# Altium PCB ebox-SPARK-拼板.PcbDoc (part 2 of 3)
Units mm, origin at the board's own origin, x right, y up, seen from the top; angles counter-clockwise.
Board outline 102 x 90 mm, 2 copper layers (Top Layer, Bottom Layer); 141 components, 68 nets, 621 pads, 146 vias.
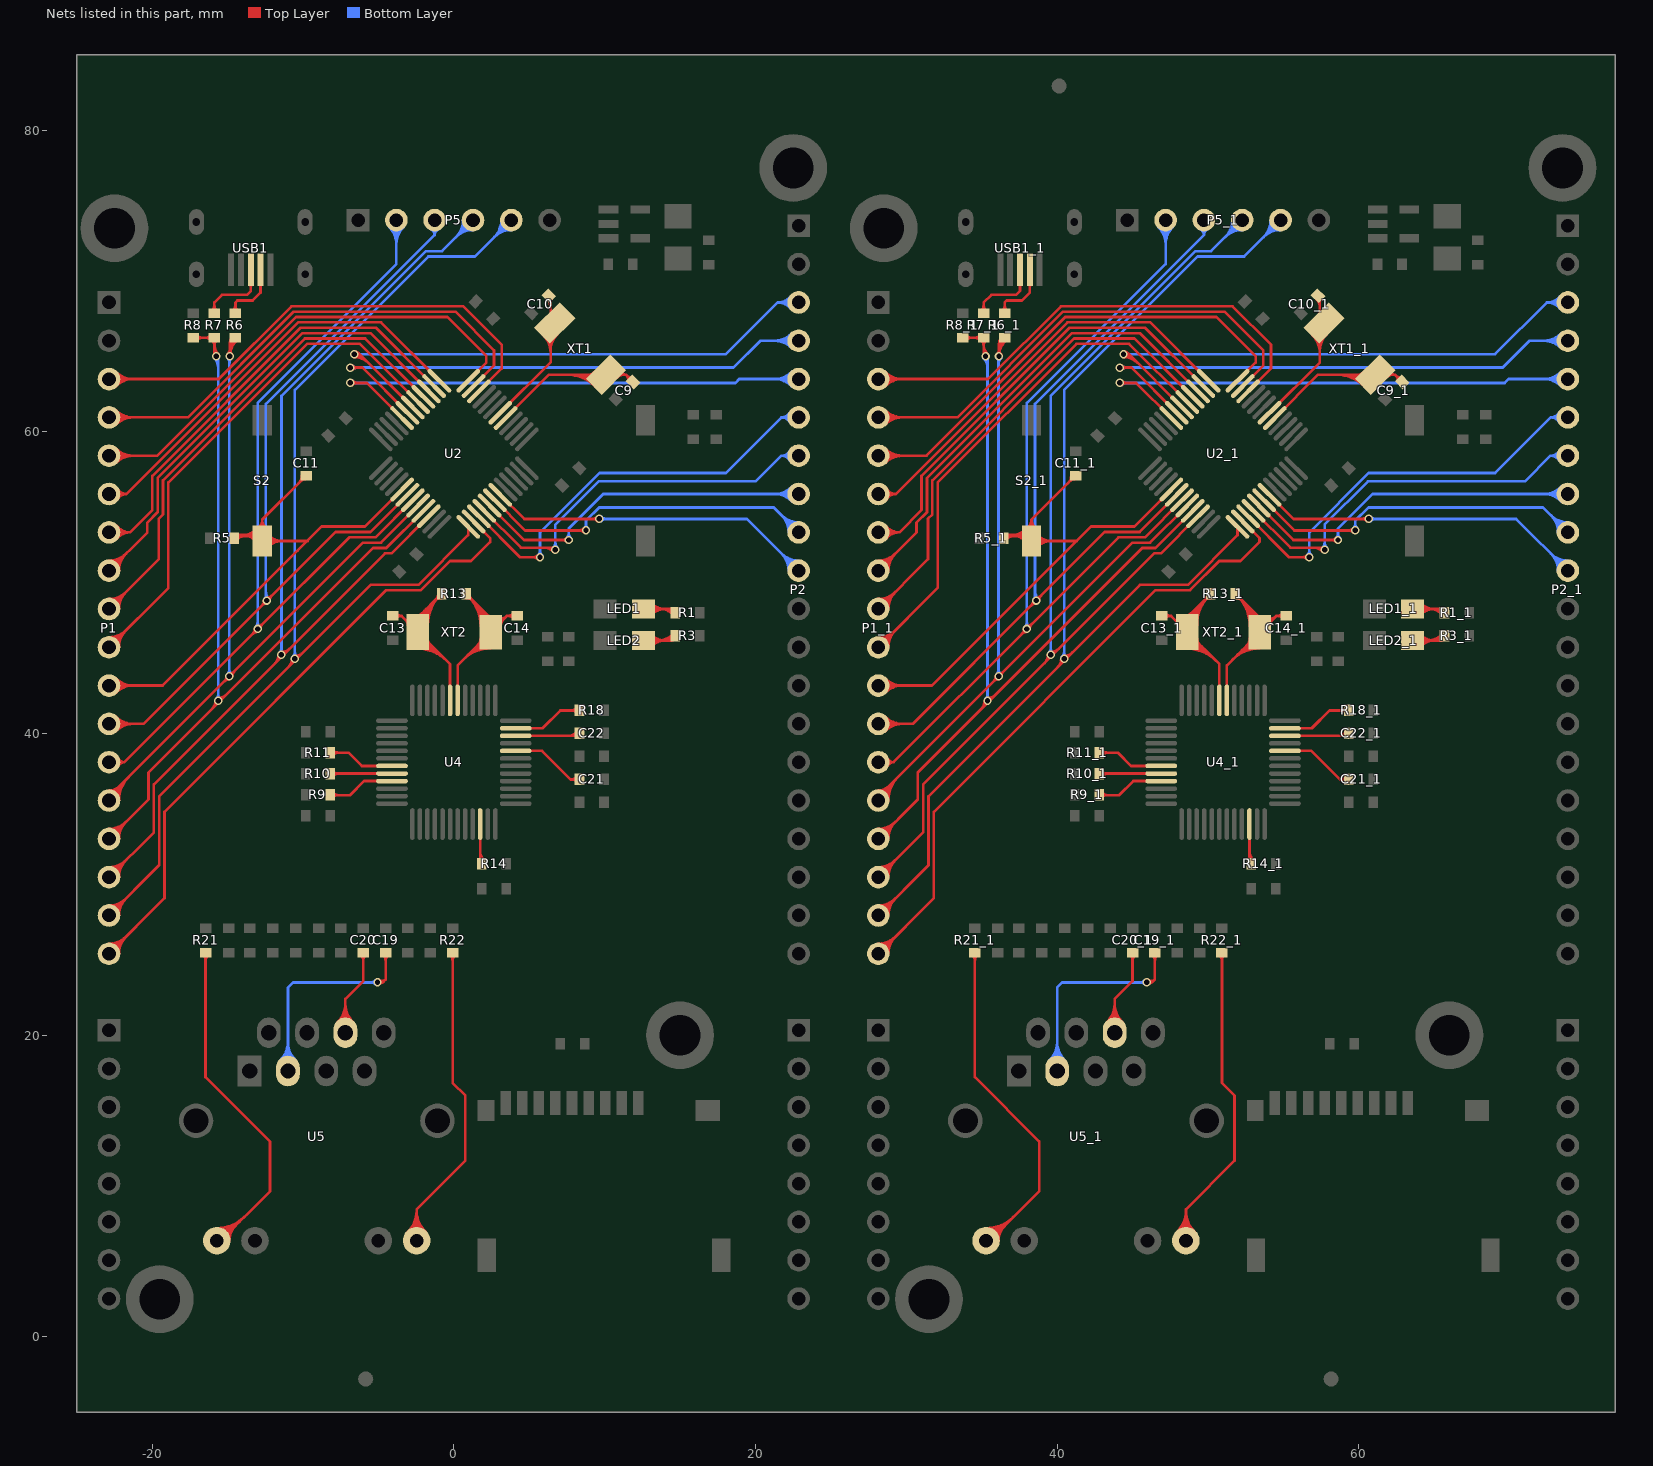
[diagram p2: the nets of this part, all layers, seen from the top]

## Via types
v1: diameter 0.559, hole 0.356, Top Layer to Bottom Layer, tented both sides, 140 vias
v2: diameter 1, hole 1, Top Layer to Bottom Layer, tented both sides, 4 vias
v3: diameter 1.27, hole 0.711, Top Layer to Bottom Layer, tented both sides, 2 vias

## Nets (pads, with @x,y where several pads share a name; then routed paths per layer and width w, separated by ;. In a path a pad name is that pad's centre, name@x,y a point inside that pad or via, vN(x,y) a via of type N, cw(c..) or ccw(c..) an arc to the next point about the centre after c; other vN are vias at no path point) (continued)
NetC9_1: C9.1 C9_1.1 U2.5 U2_1.5 XT1.1 XT1_1.1 | length 37.6
  Top Layer w0.178: U2.5@3.429,60.916 6.303,63.79 XT1.1@10.088,63.79 11.401,63.79 ; 7.527,63.79 cw(c7.527,61.228) XT1.1@9.338,63.04 ; 7.956,63.79 cw(c7.956,61.657) XT1.1@9.464,63.165 ; 8.385,63.79 cw(c8.385,62.087) XT1.1@9.589,63.291 ; 8.814,63.79 cw(c8.814,62.516) XT1.1@9.715,63.417 ; 8.892,63.79 ccw(c8.892,64.42) XT1.1@9.338,63.974 ; XT1.1@10.839,63.605 cw(c11.284,63.159) 11.284,63.79 ; XT1.1@10.853,64.115 ccw(c11.207,64.145) 11.207,63.79 ; XT1.1@11.03,64.13 ccw(c11.401,64.162) 11.401,63.79 ; C9.1@11.604,63.358 ccw(c11.052,63.358) 11.443,63.748 ccw(c11.833,64.138) C9.1@11.833,63.586 ; C9.1@11.878,63.313 11.401,63.79 ; U2_1.5@54.429,60.916 57.303,63.79 XT1_1.1@61.088,63.79 62.401,63.79 ; 58.527,63.79 cw(c58.527,61.228) XT1_1.1@60.338,63.04 ; 58.956,63.79 cw(c58.956,61.657) XT1_1.1@60.464,63.165 ; 59.385,63.79 cw(c59.385,62.087) XT1_1.1@60.589,63.291 ; 59.814,63.79 cw(c59.814,62.516) XT1_1.1@60.715,63.417 ; 59.892,63.79 ccw(c59.892,64.42) XT1_1.1@60.338,63.974 ; XT1_1.1@61.839,63.605 cw(c62.284,63.159) 62.284,63.79 ; XT1_1.1@61.853,64.115 ccw(c62.207,64.145) 62.207,63.79 ; XT1_1.1@62.03,64.13 ccw(c62.401,64.162) 62.401,63.79 ; C9_1.1@62.604,63.358 ccw(c62.052,63.358) 62.443,63.748 ccw(c62.833,64.138) C9_1.1@62.833,63.586 ; C9_1.1@62.878,63.313 62.401,63.79
NetC10_1: C10.1 C10_1.1 U2.6 U2_1.6 XT1.2 XT1_1.2 | length 30.8
  Top Layer w0.178: U2.6@3.076,61.269 6.417,64.61 6.417,68.647 6.417,68.901 C10.1@6.29,69.028 ; XT1.2@5.908,66.435 cw(c4.68,65.207) 6.417,65.207 ; XT1.2@6.034,66.56 cw(c5.109,65.636) 6.417,65.636 ; XT1.2@6.159,66.686 cw(c5.538,66.065) XT1.2@6.417,66.065 ; C10.1@6.173,68.821 cw(c5.585,68.233) 6.417,68.233 ; C10.1@6.299,68.947 cw(c6.014,68.662) C10.1@6.417,68.662 ; 6.417,65.406 cw(c7.872,65.406) XT1.2@6.843,66.435 ; 6.417,65.835 cw(c7.443,65.835) XT1.2@6.717,66.56 ; C10.1@6.417,68.629 cw(c6.688,68.629) C10.1@6.496,68.821 ; U2_1.6@54.076,61.269 57.417,64.61 57.417,68.647 57.417,68.901 C10_1.1@57.29,69.028 ; XT1_1.2@56.908,66.435 cw(c55.68,65.207) 57.417,65.207 ; XT1_1.2@57.034,66.56 cw(c56.109,65.636) 57.417,65.636 ; XT1_1.2@57.159,66.686 cw(c56.538,66.065) XT1_1.2@57.417,66.065 ; C10_1.1@57.173,68.821 cw(c56.585,68.233) 57.417,68.233 ; C10_1.1@57.299,68.947 cw(c57.014,68.662) C10_1.1@57.417,68.662 ; 57.417,65.406 cw(c58.872,65.406) XT1_1.2@57.843,66.435 ; 57.417,65.835 cw(c58.443,65.835) XT1_1.2@57.717,66.56 ; C10_1.1@57.417,68.629 cw(c57.688,68.629) C10_1.1@57.496,68.821
NetC13_2: C13.2 C13_1.2 R13.2 R13_1.2 U4.31 U4_1.31 XT2.2 XT2_1.2 | length 55.4
  Top Layer w0.178: C13.2@-4.064,47.803 -3.454,47.803 ; C13.2@-3.838,47.642 cw(c-3.454,47.265) -3.454,47.803 ; C13.2@-3.838,47.963 ccw(c-3.454,48.341) -3.454,47.803 ; -3.198,47.546 cw(c-3.558,47.186) XT2.2@-3.049,47.186 ; XT2.2@-2.438,47.186 cw(c-1.315,47.186) -2.109,47.98 ; XT2.2@-2.388,45.625 cw(c-2.388,42.942) -0.491,44.839 ; XT2.2@-2.388,45.803 cw(c-2.388,43.55) -0.794,45.143 ; XT2.2@-2.388,45.98 cw(c-2.388,44.157) -1.098,45.446 ; XT2.2@-2.388,46.158 cw(c-2.388,44.764) -1.401,45.75 ; XT2.2@-2.388,47.847 ccw(c-2.388,48.199) -2.139,47.95 ; XT2.2@-2.26,47.186 cw(c-0.708,47.186) -1.805,48.283 ; XT2.2@-2.082,47.186 cw(c-0.101,47.186) -1.502,48.587 ; XT2.2@-1.904,47.186 cw(c0.506,47.186) -1.198,48.891 ; XT2.2@-1.727,46.286 ccw(c-1.217,46.286) -1.577,45.926 ; XT2.2@-1.727,47.186 cw(c1.113,47.186) R13.2@-0.895,49.194 ; -1.311,48.777 cw(c-0.813,48.279) R13.2@-0.813,48.984 ; -1.158,48.931 ccw(c-1.44,49.212) R13.2@-1.041,49.212 ; R13.2@-0.813,49.276 -2.388,47.701 XT2.2@-2.388,46.736 ; U4.31@-0.25,42.2 -0.25,44.598 XT2.2@-2.388,46.736 ; C13_1.2@46.936,47.803 47.546,47.803 XT2_1.2@48.612,46.736 ; C13_1.2@47.162,47.642 cw(c47.546,47.265) 47.546,47.803 cw(c47.546,48.341) C13_1.2@47.162,47.963 ; 47.802,47.546 cw(c47.442,47.186) XT2_1.2@47.951,47.186 ; XT2_1.2@48.562,47.186 cw(c49.685,47.186) 48.891,47.98 ; XT2_1.2@48.612,45.625 cw(c48.612,42.942) 50.509,44.839 ; XT2_1.2@48.612,45.803 cw(c48.612,43.55) 50.206,45.143 ; XT2_1.2@48.612,45.98 cw(c48.612,44.157) 49.902,45.446 ; XT2_1.2@48.612,46.158 cw(c48.612,44.764) 49.599,45.75 ; XT2_1.2@48.612,47.847 ccw(c48.612,48.199) 48.861,47.95 ; XT2_1.2@48.74,47.186 cw(c50.292,47.186) 49.195,48.283 ; XT2_1.2@48.918,47.186 cw(c50.899,47.186) 49.498,48.587 ; XT2_1.2@49.096,47.186 cw(c51.506,47.186) 49.802,48.891 ; XT2_1.2@49.273,46.286 ccw(c49.783,46.286) 49.423,45.926 ; XT2_1.2@49.273,47.186 cw(c52.113,47.186) R13_1.2@50.105,49.194 ; 49.689,48.777 cw(c50.187,48.279) R13_1.2@50.187,48.984 ; 49.842,48.931 ccw(c49.56,49.212) R13_1.2@49.959,49.212 ; R13_1.2@50.187,49.276 48.612,47.701 XT2_1.2@48.612,46.736 ; U4_1.31@50.75,42.2 50.75,44.598 XT2_1.2@48.612,46.736 ; -3.454,47.803 XT2.2@-2.388,46.736
NetC14_1: C14.1 C14_1.1 R13.1 R13_1.1 U4.30 U4_1.30 XT2.1 XT2_1.1 | length 60.2
  Top Layer w0.178: U4.30@0.25,42.2 0.25,44.522 XT2.1@2.438,46.711 ; 0.627,44.899 cw(c2.438,43.088) XT2.1@2.438,45.649 ; R13.1@0.813,48.984 cw(c0.813,48.279) 1.311,48.777 ; R13.1@0.813,49.276 2.438,47.65 XT2.1@2.438,46.711 ; R13.1@0.928,49.161 cw(c-1.122,47.111) XT2.1@1.777,47.111 ; 0.931,45.203 cw(c2.438,43.695) XT2.1@2.438,45.827 ; R13.1@1.041,49.212 ccw(c1.44,49.212) 1.158,48.931 ; 1.232,48.857 cw(c-0.515,47.111) XT2.1@1.955,47.111 ; 1.234,45.506 cw(c2.438,44.302) XT2.1@2.438,46.005 ; 1.535,48.554 cw(c0.092,47.111) XT2.1@2.133,47.111 ; 1.538,45.81 cw(c2.438,44.909) XT2.1@2.438,46.183 ; 1.593,45.865 ccw(c1.147,46.311) XT2.1@1.777,46.311 ; 1.839,48.25 cw(c0.699,47.111) XT2.1@2.311,47.111 ; 2.142,47.947 cw(c1.306,47.111) XT2.1@2.489,47.111 ; XT2.1@2.231,47.857 ccw(c2.438,48.065) XT2.1@2.438,47.772 ; XT2.1@2.585,47.379 ccw(c2.831,47.83) 3.194,47.467 ; XT2.1@2.67,47.535 ccw(c2.949,48.048) 3.363,47.635 ; XT2.1@2.755,47.691 ccw(c3.068,48.265) 3.531,47.803 ; XT2.1@3.099,47.111 cw(c3.73,47.111) 3.284,47.556 ; C14.1@3.966,47.641 ccw(c3.576,47.251) 3.576,47.803 ccw(c3.576,48.355) C14.1@3.966,47.964 ; C14.1@4.191,47.803 3.531,47.803 ; U4_1.30@51.25,42.2 51.25,44.522 XT2_1.1@53.438,46.711 ; 51.627,44.899 cw(c53.438,43.088) XT2_1.1@53.438,45.649 ; R13_1.1@51.813,48.984 cw(c51.813,48.279) 52.311,48.777 ; R13_1.1@51.813,49.276 53.438,47.65 XT2_1.1@53.438,46.711 ; R13_1.1@51.928,49.161 cw(c49.878,47.111) XT2_1.1@52.777,47.111 ; 51.931,45.203 cw(c53.438,43.695) XT2_1.1@53.438,45.827 ; R13_1.1@52.041,49.212 ccw(c52.44,49.212) 52.158,48.931 ; 52.232,48.857 cw(c50.485,47.111) XT2_1.1@52.955,47.111 ; 52.234,45.506 cw(c53.438,44.302) XT2_1.1@53.438,46.005 ; 52.535,48.554 cw(c51.092,47.111) XT2_1.1@53.133,47.111 ; 52.538,45.81 cw(c53.438,44.909) XT2_1.1@53.438,46.183 ; 52.593,45.865 ccw(c52.147,46.311) XT2_1.1@52.777,46.311 ; 52.839,48.25 cw(c51.699,47.111) XT2_1.1@53.311,47.111 ; 53.142,47.947 cw(c52.306,47.111) XT2_1.1@53.489,47.111 ; XT2_1.1@53.231,47.857 ccw(c53.438,48.065) XT2_1.1@53.438,47.772 ; XT2_1.1@53.585,47.379 ccw(c53.831,47.83) 54.194,47.467 ; XT2_1.1@53.67,47.535 ccw(c53.949,48.048) 54.363,47.635 ; XT2_1.1@53.755,47.691 ccw(c54.068,48.265) 54.531,47.803 ; XT2_1.1@54.099,47.111 cw(c54.73,47.111) 54.284,47.556 ; C14_1.1@54.966,47.641 ccw(c54.576,47.251) 54.576,47.803 ccw(c54.576,48.355) C14_1.1@54.966,47.964 ; C14_1.1@55.191,47.803 54.531,47.803 ; XT2.1@2.438,46.711 3.531,47.803 ; XT2_1.1@53.438,46.711 54.531,47.803
NetC19_1: C19.1 C19_1.1 U5.3 U5_1.3 | length 44.8
  Top Layer w0.178: v1(-5.061,23.509) -4.711,23.509 -4.521,23.698 ; v1@-5.054,23.519 ccw(c-4.88,23.761) -4.669,23.55 ; v1@-4.95,23.663 ccw(c-4.756,23.933) -4.521,23.698 ; C19.1@-4.683,25.315 cw(c-5.073,24.924) -4.521,24.924 cw(c-3.969,24.924) C19.1@-4.36,25.315 ; C19.1@-4.521,25.476 -4.521,23.698 ; v1(45.939,23.509) 46.289,23.509 46.479,23.698 ; v1@45.946,23.519 ccw(c46.12,23.761) 46.331,23.55 ; v1@46.05,23.663 ccw(c46.244,23.933) 46.479,23.698 ; C19_1.1@46.317,25.315 cw(c45.927,24.924) 46.479,24.924 cw(c47.031,24.924) C19_1.1@46.64,25.315 ; C19_1.1@46.479,25.476 46.479,23.698
  Bottom Layer w0.178: U5.3@-11.493,18.35 ccw(c-12.685,19.543) -10.999,19.543 ccw(c-9.312,19.543) U5.3@-10.505,18.35 ; U5.3@-11.367,18.224 ccw(c-12.256,19.113) -10.999,19.113 ccw(c-9.742,19.113) U5.3@-10.63,18.224 ; U5.3@-11.241,18.099 ccw(c-11.826,18.684) -10.999,18.684 ccw(c-10.171,18.684) U5.3@-10.756,18.099 ; U5.3@-10.999,17.628 -10.999,23.164 -10.668,23.495 -5.064,23.495 -5.061,23.498 v1(-5.061,23.509) ; -5.554,23.495 ccw(c-5.554,24.001) v1@-5.196,23.643 ; -5.488,23.495 cw(c-5.488,23.081) v1@-5.196,23.374 ; U5_1.3@39.507,18.35 ccw(c38.315,19.543) 40.001,19.543 ccw(c41.688,19.543) U5_1.3@40.495,18.35 ; U5_1.3@39.633,18.224 ccw(c38.744,19.113) 40.001,19.113 ccw(c41.258,19.113) U5_1.3@40.37,18.224 ; U5_1.3@39.759,18.099 ccw(c39.174,18.684) 40.001,18.684 ccw(c40.829,18.684) U5_1.3@40.244,18.099 ; U5_1.3@40.001,17.628 40.001,23.164 40.332,23.495 45.936,23.495 45.939,23.498 v1(45.939,23.509) ; 45.446,23.495 ccw(c45.446,24.001) v1@45.804,23.643 ; 45.512,23.495 cw(c45.512,23.081) v1@45.804,23.374
NetC20_1: C20.1 C20_1.1 U5.6 U5_1.6 | length 29.6
  Top Layer w0.178: U5.6@-7.683,20.89 ccw(c-8.875,22.083) -7.189,22.083 ccw(c-5.502,22.083) U5.6@-6.695,20.89 ; U5.6@-7.557,20.764 ccw(c-8.446,21.653) -7.189,21.653 ccw(c-5.932,21.653) U5.6@-6.82,20.764 ; U5.6@-7.431,20.639 ccw(c-8.016,21.224) -7.189,21.224 ccw(c-6.361,21.224) U5.6@-6.946,20.639 ; U5.6@-7.189,20.168 -7.189,22.402 -6.003,23.588 C20.1@-6.003,25.476 -6.003,24.13 ; U5_1.6@43.317,20.89 ccw(c42.125,22.083) 43.811,22.083 ccw(c45.498,22.083) U5_1.6@44.305,20.89 ; U5_1.6@43.443,20.764 ccw(c42.554,21.653) 43.811,21.653 ccw(c45.068,21.653) U5_1.6@44.18,20.764 ; U5_1.6@43.569,20.639 ccw(c42.984,21.224) 43.811,21.224 ccw(c44.639,21.224) U5_1.6@44.054,20.639 ; U5_1.6@43.811,20.168 43.811,22.402 44.997,23.588 C20_1.1@44.997,25.476 44.997,24.13 ; -6.003,24.924 cw(c-5.451,24.924) -5.841,25.315 ccw(c-5.451,24.924) -6.003,24.924 ; -6.003,24.924 ccw(c-6.555,24.924) -6.165,25.315 cw(c-6.555,24.924) -6.003,24.924 ; 44.997,24.924 cw(c45.549,24.924) 45.159,25.315 ccw(c45.549,24.924) 44.997,24.924 ; 44.997,24.924 ccw(c44.445,24.924) 44.835,25.315 cw(c44.445,24.924) 44.997,24.924
NetC21_2: C21.2 C21_1.2 U4.20 U4_1.20 | length 11.8
  Top Layer w0.178: U4.20@4.1,38.85 5.854,38.85 7.747,36.957 C21.2@8.331,36.957 ; C21.2@8.17,36.795 ccw(c7.779,36.405) 7.779,36.957 ccw(c7.779,37.509) C21.2@8.17,37.119 ; U4_1.20@55.1,38.85 56.854,38.85 58.747,36.957 C21_1.2@59.331,36.957 ; C21_1.2@59.17,36.795 ccw(c58.779,36.405) 58.779,36.957 ccw(c58.779,37.509) C21_1.2@59.17,37.119
NetC22_2: C22.2 C22_1.2 U4.22 U4_1.22 | length 11
  Top Layer w0.178: U4.22@4.1,39.85 8.176,39.85 C22.2@8.331,40.005 ; 7.558,39.85 ccw(c7.558,40.714) C22.2@8.17,40.103 ; 7.988,39.85 ccw(c7.988,40.285) C22.2@8.295,39.977 ; 8,39.85 cw(c8,39.611) C22.2@8.17,39.78 ; U4_1.22@55.1,39.85 59.176,39.85 C22_1.2@59.331,40.005 ; 58.558,39.85 ccw(c58.558,40.714) C22_1.2@59.17,40.103 ; 58.988,39.85 ccw(c58.988,40.285) C22_1.2@59.295,39.977 ; 59,39.85 cw(c59,39.611) C22_1.2@59.17,39.78
NetLED1_A: LED1.A LED1_1.A R1.2 R1_1.2 | length 13.6
  Top Layer w0.178: LED1.A@12.573,48.26 R1.2@14.427,48.26 ; LED1.A@12.963,48.007 cw(c13.575,47.395) 13.575,48.26 cw(c13.575,49.125) LED1.A@12.963,48.513 ; LED1.A@13.089,47.881 cw(c14.004,46.966) 14.004,48.26 cw(c14.004,49.554) LED1.A@13.089,48.639 ; 13.669,48.26 cw(c13.669,47.058) R1.2@14.52,47.908 ; 14.099,48.26 cw(c14.099,47.487) R1.2@14.645,48.034 ; LED1_1.A@63.573,48.26 R1_1.2@65.427,48.26 ; LED1_1.A@63.963,48.007 cw(c64.575,47.395) 64.575,48.26 cw(c64.575,49.125) LED1_1.A@63.963,48.513 ; LED1_1.A@64.089,47.881 cw(c65.004,46.966) 65.004,48.26 cw(c65.004,49.554) LED1_1.A@64.089,48.639 ; 64.669,48.26 cw(c64.669,47.058) R1_1.2@65.52,47.908 ; 65.099,48.26 cw(c65.099,47.487) R1_1.2@65.645,48.034
NetLED2_A: LED2.A LED2_1.A R3.2 R3_1.2 | length 15.9
  Top Layer w0.178: LED2.A@12.573,46.164 14.364,46.164 R3.2@14.681,46.482 ; LED2.A@12.963,45.911 cw(c13.575,45.299) 13.575,46.164 cw(c13.575,47.03) LED2.A@12.963,46.418 ; LED2.A@13.089,45.785 cw(c14.004,44.87) 14.004,46.164 cw(c14.004,47.459) LED2.A@13.089,46.544 ; 13.516,46.164 ccw(c13.516,47.584) R3.2@14.52,46.58 ; 13.945,46.164 ccw(c13.945,47.154) R3.2@14.645,46.454 ; R3.2@14.375,46.164 ccw(c14.375,46.725) R3.2@14.771,46.329 ; LED2_1.A@63.573,46.164 65.364,46.164 R3_1.2@65.681,46.482 ; LED2_1.A@63.963,45.911 cw(c64.575,45.299) 64.575,46.164 cw(c64.575,47.03) LED2_1.A@63.963,46.418 ; LED2_1.A@64.089,45.785 cw(c65.004,44.87) 65.004,46.164 cw(c65.004,47.459) LED2_1.A@64.089,46.544 ; 64.516,46.164 ccw(c64.516,47.584) R3_1.2@65.52,46.58 ; 64.945,46.164 ccw(c64.945,47.154) R3_1.2@65.645,46.454 ; R3_1.2@65.375,46.164 ccw(c65.375,46.725) R3_1.2@65.771,46.329
NetR6_2: R6.2 R6_1.2 USB1.2 USB1_1.2 | length 11.2
  Top Layer w0.178: R6.2@-14.64,68.03 ccw(c-15.03,68.421) -14.478,68.421 ccw(c-13.926,68.421) R6.2@-14.316,68.03 ; R6.2@-14.478,67.869 -14.478,68.58 -14.351,68.707 -13.335,68.707 -12.812,69.23 USB1.2@-12.812,70.881 ; USB1.2@-12.891,69.8 cw(c-13.08,69.611) -12.812,69.611 cw(c-12.544,69.611) USB1.2@-12.733,69.8 ; R6_1.2@36.36,68.03 ccw(c35.97,68.421) 36.522,68.421 ccw(c37.074,68.421) R6_1.2@36.684,68.03 ; R6_1.2@36.522,67.869 36.522,68.58 36.649,68.707 37.665,68.707 38.188,69.23 USB1_1.2@38.188,70.881 ; USB1_1.2@38.109,69.8 cw(c37.92,69.611) 38.188,69.611 cw(c38.456,69.611) USB1_1.2@38.267,69.8
NetR7_2: R7.2 R7_1.2 USB1.3 USB1_1.3 | length 12.5
  Top Layer w0.178: R7.2@-16.037,68.03 ccw(c-16.427,68.421) -15.875,68.421 ccw(c-15.323,68.421) R7.2@-15.713,68.03 ; R7.2@-15.875,67.869 -15.875,68.58 -15.367,69.088 -13.716,69.088 -13.462,69.342 USB1.3@-13.462,70.881 ; USB1.3@-13.541,69.8 cw(c-13.73,69.611) -13.462,69.611 cw(c-13.194,69.611) USB1.3@-13.383,69.8 ; R7_1.2@34.963,68.03 ccw(c34.573,68.421) 35.125,68.421 ccw(c35.677,68.421) R7_1.2@35.287,68.03 ; R7_1.2@35.125,67.869 35.125,68.58 35.633,69.088 37.284,69.088 37.538,69.342 USB1_1.3@37.538,70.881 ; USB1_1.3@37.459,69.8 cw(c37.27,69.611) 37.538,69.611 cw(c37.806,69.611) USB1_1.3@37.617,69.8
NetR9_1: R9.1 R9_1.1 U4.45 U4_1.45 | length 10.7
  Top Layer w0.178: R9.1@-8.204,35.909 -6.89,35.909 -5.949,36.85 U4.45@-4.1,36.85 ; R9.1@-8.043,35.779 cw(c-7.729,35.466) -7.729,35.909 ; R9.1@-8.043,36.103 ccw(c-7.576,36.57) -7.576,35.909 ; R9_1.1@42.796,35.909 44.11,35.909 45.051,36.85 U4_1.45@46.9,36.85 ; R9_1.1@42.957,35.779 cw(c43.271,35.466) 43.271,35.909 ; R9_1.1@42.957,36.103 ccw(c43.424,36.57) 43.424,35.909
NetR10_1: R10.1 R10_1.1 U4.44 U4_1.44 | length 10
  Top Layer w0.178: R10.1@-8.204,37.338 -8.192,37.35 U4.44@-4.1,37.35 ; R10.1@-8.043,37.176 cw(c-7.623,36.757) -7.623,37.35 ; R10.1@-8.043,37.5 ccw(c-7.681,37.861) -7.681,37.35 ; R10_1.1@42.796,37.338 42.808,37.35 U4_1.44@46.9,37.35 ; R10_1.1@42.957,37.176 cw(c43.377,36.757) 43.377,37.35 ; R10_1.1@42.957,37.5 ccw(c43.319,37.861) 43.319,37.35
NetR11_1: R11.1 R11_1.1 U4.43 U4_1.43 | length 10.7
  Top Layer w0.178: R11.1@-8.204,38.735 -6.985,38.735 -6.1,37.85 U4.43@-4.1,37.85 ; R11.1@-8.043,38.573 cw(c-7.652,38.183) -7.652,38.735 cw(c-7.652,39.287) R11.1@-8.043,38.897 ; R11_1.1@42.796,38.735 44.015,38.735 44.9,37.85 U4_1.43@46.9,37.85 ; R11_1.1@42.957,38.573 cw(c43.348,38.183) 43.348,38.735 cw(c43.348,39.287) R11_1.1@42.957,38.897
NetR14_1: R14.1 R14_1.1 U4.10 U4_1.10 | length 7.3
  Top Layer w0.178: R14.1@1.693,31.594 ccw(c1.554,31.733) R14.1@1.75,31.733 ; R14.1@1.75,31.6 U4.10@1.75,34 ; 1.75,31.807 ccw(c2.228,31.807) R14.1@1.89,31.468 ; 1.75,32.236 ccw(c2.658,32.236) R14.1@2.016,31.594 ; R14_1.1@52.693,31.594 ccw(c52.554,31.733) R14_1.1@52.75,31.733 ; R14_1.1@52.75,31.6 U4_1.10@52.75,34 ; 52.75,31.807 ccw(c53.228,31.807) R14_1.1@52.89,31.468 ; 52.75,32.236 ccw(c53.658,32.236) R14_1.1@53.016,31.594
NetR18_2: R18.2 R18_1.2 U4.23 U4_1.23 | length 11.2
  Top Layer w0.178: U4.23@4.1,40.35 5.878,40.35 7.057,41.529 R18.2@8.331,41.529 ; R18.2@8.17,41.367 ccw(c7.779,40.977) 7.779,41.529 ccw(c7.779,42.081) R18.2@8.17,41.691 ; U4_1.23@55.1,40.35 56.878,40.35 58.057,41.529 R18_1.2@59.331,41.529 ; R18_1.2@59.17,41.367 ccw(c58.779,40.977) 58.779,41.529 ccw(c58.779,42.081) R18_1.2@59.17,41.691
NetR21_2: R21.2 R21_1.2 U5.9 U5_1.9 | length 62.6
  Top Layer w0.178: R21.2@-16.621,25.315 cw(c-17.011,24.924) -16.459,24.924 cw(c-15.907,24.924) R21.2@-16.298,25.315 ; R21.2@-16.459,25.476 -16.459,17.221 -12.192,12.954 -12.192,9.652 -15.466,6.378 U5.9@-15.714,6.378 ; U5.9@-15.714,6.67 ccw(c-15.714,7.972) -14.793,7.051 ; U5.9@-15.714,6.848 ccw(c-15.714,8.579) -14.489,7.355 ; U5.9@-15.714,7.025 ccw(c-15.714,9.186) -14.186,7.658 ; U5.9@-15.714,7.203 ccw(c-15.714,9.793) -13.882,7.962 ; U5.9@-15.066,6.378 cw(c-14.099,6.378) -14.783,7.061 ; U5.9@-14.888,6.378 cw(c-13.492,6.378) -14.479,7.365 ; R21_1.2@34.379,25.315 cw(c33.989,24.924) 34.541,24.924 cw(c35.093,24.924) R21_1.2@34.702,25.315 ; R21_1.2@34.541,25.476 34.541,17.221 38.808,12.954 38.808,9.652 35.534,6.378 U5_1.9@35.286,6.378 ; U5_1.9@35.286,6.67 ccw(c35.286,7.972) 36.207,7.051 ; U5_1.9@35.286,6.848 ccw(c35.286,8.579) 36.511,7.355 ; U5_1.9@35.286,7.025 ccw(c35.286,9.186) 36.814,7.658 ; U5_1.9@35.286,7.203 ccw(c35.286,9.793) 37.118,7.962 ; U5_1.9@35.934,6.378 cw(c36.901,6.378) 36.217,7.061 ; U5_1.9@36.112,6.378 cw(c37.508,6.378) 36.521,7.365
NetR22_2: R22.2 R22_1.2 U5.12 U5_1.12 | length 58
  Top Layer w0.178: U5.12@-3.048,6.961 ccw(c-4.457,8.371) -2.464,8.371 ccw(c-0.471,8.371) U5.12@-1.88,6.961 ; U5.12@-2.922,6.836 ccw(c-4.028,7.941) -2.464,7.941 ccw(c-0.901,7.941) U5.12@-2.006,6.836 ; U5.12@-2.796,6.71 ccw(c-3.599,7.512) -2.464,7.512 ccw(c-1.33,7.512) U5.12@-2.132,6.71 ; U5.12@-2.464,6.378 -2.464,8.458 0.762,11.684 0.762,16.002 -0.076,16.84 -0.076,18.085 -0.076,18.161 R22.2@-0.076,25.476 ; R22.2@-0.238,25.315 cw(c-0.628,24.924) -0.076,24.924 cw(c0.476,24.924) R22.2@0.085,25.315 ; U5_1.12@47.952,6.961 ccw(c46.543,8.371) 48.536,8.371 ccw(c50.529,8.371) U5_1.12@49.12,6.961 ; U5_1.12@48.078,6.836 ccw(c46.972,7.941) 48.536,7.941 ccw(c50.099,7.941) U5_1.12@48.994,6.836 ; U5_1.12@48.204,6.71 ccw(c47.401,7.512) 48.536,7.512 ccw(c49.67,7.512) U5_1.12@48.868,6.71 ; U5_1.12@48.536,6.378 48.536,8.458 51.762,11.684 51.762,16.002 50.924,16.84 50.924,18.085 50.924,18.161 R22_1.2@50.924,25.476 ; R22_1.2@50.762,25.315 cw(c50.372,24.924) 50.924,24.924 cw(c51.476,24.924) R22_1.2@51.085,25.315
PA0: P1.3 P1_1.3 U2.10 U2_1.10 | length 74.3
  Top Layer w0.178: P1.3@-22.86,63.5 -15.585,63.5 -10.759,68.326 0.635,68.326 3.175,65.786 3.175,64.197 U2.10@1.662,62.684 ; P1.3@-22.518,63.158 cw(c-21.693,62.333) -21.693,63.5 cw(c-21.693,64.667) P1.3@-22.518,63.842 ; P1.3@-22.393,63.033 cw(c-21.264,61.904) -21.264,63.5 cw(c-21.264,65.096) P1.3@-22.393,63.967 ; P1_1.3@28.14,63.5 35.415,63.5 40.241,68.326 51.635,68.326 54.175,65.786 54.175,64.197 U2_1.10@52.662,62.684 ; P1_1.3@28.482,63.158 cw(c29.307,62.333) 29.307,63.5 cw(c29.307,64.667) P1_1.3@28.482,63.842 ; P1_1.3@28.607,63.033 cw(c29.736,61.904) 29.736,63.5 cw(c29.736,65.096) P1_1.3@28.607,63.967
PA1: P1.4 P1_1.4 U2.11 U2_1.11 | length 73.5
  Top Layer w0.178: P1.4@-22.86,60.96 -17.622,60.96 -10.612,67.97 0.102,67.97 2.667,65.405 2.667,64.396 U2.11@1.308,63.037 ; P1.4@-22.518,60.618 cw(c-21.693,59.793) -21.693,60.96 cw(c-21.693,62.127) P1.4@-22.518,61.302 ; P1.4@-22.393,60.493 cw(c-21.264,59.364) -21.264,60.96 cw(c-21.264,62.556) P1.4@-22.393,61.427 ; P1_1.4@28.14,60.96 33.378,60.96 40.388,67.97 51.102,67.97 53.667,65.405 53.667,64.396 U2_1.11@52.308,63.037 ; P1_1.4@28.482,60.618 cw(c29.307,59.793) 29.307,60.96 cw(c29.307,62.127) P1_1.4@28.482,61.302 ; P1_1.4@28.607,60.493 cw(c29.736,59.364) 29.736,60.96 cw(c29.736,62.556) P1_1.4@28.607,61.427
PA2: P1.5 P1_1.5 U2.12 U2_1.12 | length 72.7
  Top Layer w0.178: P1.5@-22.86,58.42 -19.659,58.42 -10.465,67.615 -0.432,67.615 2.159,65.024 2.159,64.595 U2.12@0.955,63.391 ; P1.5@-22.518,58.078 cw(c-21.693,57.253) -21.693,58.42 cw(c-21.693,59.587) P1.5@-22.518,58.762 ; P1.5@-22.393,57.953 cw(c-21.264,56.824) -21.264,58.42 cw(c-21.264,60.016) P1.5@-22.393,58.887 ; P1_1.5@28.14,58.42 31.341,58.42 40.535,67.615 50.568,67.615 53.159,65.024 53.159,64.595 U2_1.12@51.955,63.391 ; P1_1.5@28.482,58.078 cw(c29.307,57.253) 29.307,58.42 cw(c29.307,59.587) P1_1.5@28.482,58.762 ; P1_1.5@28.607,57.953 cw(c29.736,56.824) 29.736,58.42 cw(c29.736,60.016) P1_1.5@28.607,58.887
PA3: P1.6 P1_1.6 U2.13 U2_1.13 | length 61.4
  Top Layer w0.178: P1.6@-22.86,55.88 -21.697,55.88 ; P1.6@-22.445,55.633 cw(c-22.01,55.373) -22.01,55.88 cw(c-22.01,56.387) P1.6@-22.445,56.127 ; P1.6@-22.292,55.542 cw(c-21.697,55.187) -21.697,55.88 ; P1.6@-22.292,56.218 ccw(c-21.697,56.573) -21.697,55.88 ; U2.13@-0.955,63.391 -4.823,67.259 -10.317,67.259 -21.697,55.88 ; P1_1.6@28.14,55.88 29.303,55.88 ; P1_1.6@28.555,55.633 cw(c28.99,55.373) 28.99,55.88 cw(c28.99,56.387) P1_1.6@28.555,56.127 ; P1_1.6@28.708,55.542 cw(c29.303,55.187) 29.303,55.88 ; P1_1.6@28.708,56.218 ccw(c29.303,56.573) 29.303,55.88 ; U2_1.13@50.045,63.391 46.177,67.259 40.683,67.259 29.303,55.88
PA4: P1.7 P1_1.7 U2.14 U2_1.14 | length 67.2
  Top Layer w0.178: P1.7@-22.86,53.34 -21.468,53.34 ; P1.7@-22.485,53.035 cw(c-21.842,52.51) -21.842,53.34 cw(c-21.842,54.17) P1.7@-22.485,53.645 ; P1.7@-22.348,52.922 cw(c-21.468,52.205) -21.468,53.34 ; P1.7@-22.348,53.758 ccw(c-21.468,54.475) -21.468,53.34 ; U2.14@-1.308,63.037 -5.175,66.904 -10.17,66.904 -19.99,57.084 -19.99,54.818 -21.468,53.34 ; P1_1.7@28.14,53.34 29.532,53.34 ; P1_1.7@28.515,53.035 cw(c29.158,52.51) 29.158,53.34 cw(c29.158,54.17) P1_1.7@28.515,53.645 ; P1_1.7@28.652,52.922 cw(c29.532,52.205) 29.532,53.34 ; P1_1.7@28.652,53.758 ccw(c29.532,54.475) 29.532,53.34 ; U2_1.14@49.692,63.037 45.825,66.904 40.83,66.904 31.01,57.084 31.01,54.818 29.532,53.34
PA5: P1.8 P1_1.8 U2.15 U2_1.15 | length 70.7
  Top Layer w0.178: P1.8@-22.86,50.8 -20.32,53.34 -20.32,53.985 -19.634,54.671 -19.634,56.937 -10.023,66.548 -5.526,66.548 U2.15@-1.662,62.684 ; P1.8@-22.86,51.283 ccw(c-22.86,52.45) -22.035,51.625 ccw(c-21.21,50.8) P1.8@-22.377,50.8 ; P1.8@-22.86,51.461 ccw(c-22.86,53.057) -21.731,51.929 ccw(c-20.603,50.8) P1.8@-22.199,50.8 ; P1_1.8@28.14,50.8 30.68,53.34 30.68,53.985 31.366,54.671 31.366,56.937 40.977,66.548 45.474,66.548 U2_1.15@49.338,62.684 ; P1_1.8@28.14,51.283 ccw(c28.14,52.45) 28.965,51.625 ccw(c29.79,50.8) P1_1.8@28.623,50.8 ; P1_1.8@28.14,51.461 ccw(c28.14,53.057) 29.269,51.929 ccw(c30.397,50.8) P1_1.8@28.801,50.8
PA6: P1.9 P1_1.9 U2.16 U2_1.16 | length 74.2
  Top Layer w0.178: P1.9@-22.86,48.26 -19.558,51.562 -19.558,54.244 -19.279,54.524 -19.279,56.789 -9.875,66.192 -5.878,66.192 U2.16@-2.015,62.33 ; P1.9@-22.86,48.743 ccw(c-22.86,49.91) -22.035,49.085 ccw(c-21.21,48.26) P1.9@-22.377,48.26 ; P1.9@-22.86,48.921 ccw(c-22.86,50.517) -21.731,49.389 ccw(c-20.603,48.26) P1.9@-22.199,48.26 ; P1_1.9@28.14,48.26 31.442,51.562 31.442,54.244 31.721,54.524 31.721,56.789 41.125,66.192 45.122,66.192 U2_1.16@48.985,62.33 ; P1_1.9@28.14,48.743 ccw(c28.14,49.91) 28.965,49.085 ccw(c29.79,48.26) P1_1.9@28.623,48.26 ; P1_1.9@28.14,48.921 ccw(c28.14,50.517) 29.269,49.389 ccw(c30.397,48.26) P1_1.9@28.801,48.26
PA7: P1.10 P1_1.10 U2.17 U2_1.17 | length 77.7
  Top Layer w0.178: P1.10@-22.86,45.72 -18.923,49.657 -18.923,56.642 -9.728,65.837 -6.229,65.837 U2.17@-2.369,61.976 ; P1.10@-22.86,46.203 ccw(c-22.86,47.37) -22.035,46.545 ccw(c-21.21,45.72) P1.10@-22.377,45.72 ; P1.10@-22.86,46.381 ccw(c-22.86,47.977) -21.731,46.849 ccw(c-20.603,45.72) P1.10@-22.199,45.72 ; P1_1.10@28.14,45.72 32.077,49.657 32.077,56.642 41.272,65.837 44.771,65.837 U2_1.17@48.631,61.976 ; P1_1.10@28.14,46.203 ccw(c28.14,47.37) 28.965,46.545 ccw(c29.79,45.72) P1_1.10@28.623,45.72 ; P1_1.10@28.14,46.381 ccw(c28.14,47.977) 29.269,46.849 ccw(c30.397,45.72) P1_1.10@28.801,45.72
PA8: C11.2 C11_1.2 P1.11 P1_1.11 R5.2 R5_1.2 S2.1 S2_1.1 U2.29 U2_1.29 | length 97.4
  Top Layer w0.178: P1.11@-22.86,43.18 -19.304,43.18 -10.36,52.124 -8.763,53.721 -5.887,53.721 U2.29@-3.429,56.178 ; P1.11@-22.518,42.838 cw(c-21.693,42.013) -21.693,43.18 cw(c-21.693,44.347) P1.11@-22.518,43.522 ; P1.11@-22.393,42.713 cw(c-21.264,41.584) -21.264,43.18 cw(c-21.264,44.776) P1.11@-22.393,43.647 ; S2.1@-13.006,53.602 ccw(c-13.395,54.178) -12.7,54.178 ; S2.1@-12.906,53.455 ccw(c-13.169,53.843) -12.7,53.843 ccw(c-12.231,53.843) S2.1@-12.494,53.455 ; S2.1@-12.44,52.509 cw(c-11.811,51.88) -11.811,52.769 cw(c-11.811,53.658) S2.1@-12.44,53.029 ; S2.1@-12.394,53.602 cw(c-12.005,54.178) -12.7,54.178 ; S2.1@-12.314,52.383 cw(c-11.382,51.451) -11.382,52.769 cw(c-11.382,54.087) S2.1@-12.314,53.155 ; -10.278,56.601 ccw(c-10.776,57.099) C11.2@-10.071,57.099 ; -10.124,56.754 cw(c-9.843,56.472) C11.2@-9.843,56.871 ; C11.2@-9.779,57.099 -12.7,54.178 ; -9.692,52.769 S2.1@-12.7,52.769 -12.7,54.178 ; P1_1.11@28.14,43.18 31.696,43.18 40.64,52.124 42.237,53.721 45.113,53.721 U2_1.29@47.571,56.178 ; P1_1.11@28.482,42.838 cw(c29.307,42.013) 29.307,43.18 cw(c29.307,44.347) P1_1.11@28.482,43.522 ; P1_1.11@28.607,42.713 cw(c29.736,41.584) 29.736,43.18 cw(c29.736,44.776) P1_1.11@28.607,43.647 ; S2_1.1@37.994,53.602 ccw(c37.605,54.178) 38.3,54.178 ; S2_1.1@38.094,53.455 ccw(c37.831,53.843) 38.3,53.843 ccw(c38.769,53.843) S2_1.1@38.506,53.455 ; S2_1.1@38.56,52.509 cw(c39.189,51.88) 39.189,52.769 cw(c39.189,53.658) S2_1.1@38.56,53.029 ; S2_1.1@38.606,53.602 cw(c38.995,54.178) 38.3,54.178 ; S2_1.1@38.686,52.383 cw(c39.618,51.451) 39.618,52.769 cw(c39.618,54.087) S2_1.1@38.686,53.155 ; 40.722,56.601 ccw(c40.224,57.099) C11_1.2@40.929,57.099 ; 40.876,56.754 cw(c41.157,56.472) C11_1.2@41.157,56.871 ; C11_1.2@41.221,57.099 38.3,54.178 ; 41.308,52.769 S2_1.1@38.3,52.769 38.3,54.178
  Top Layer w0.254: R5.2@-14.419,52.888 cw(c-13.818,52.287) -13.818,53.137 ; R5.2@-14.351,53.137 S2.1@-13.068,53.137 ; -13.958,53.137 ccw(c-13.958,54.408) S2.1@-13.059,53.509 ; -13.895,53.137 cw(c-13.895,51.955) S2.1@-13.059,52.791 ; -13.345,53.137 ccw(c-13.345,53.795) S2.1@-12.88,53.33 ; R5_1.2@36.581,52.888 cw(c37.182,52.287) 37.182,53.137 ; R5_1.2@36.649,53.137 S2_1.1@37.932,53.137 ; 37.042,53.137 ccw(c37.042,54.408) S2_1.1@37.941,53.509 ; 37.105,53.137 cw(c37.105,51.955) S2_1.1@37.941,52.791 ; 37.655,53.137 ccw(c37.655,53.795) S2_1.1@38.12,53.33
PA9: P1.12 P1_1.12 P5.3 P5_1.3 U2.30 U2_1.30 | length 127.4
  Top Layer w0.178: P1.12@-22.86,40.64 -20.574,40.64 v1(-12.398,48.816) -7.849,53.365 -5.535,53.365 U2.30@-3.076,55.825 ; P1.12@-22.518,40.298 cw(c-21.693,39.473) -21.693,40.64 cw(c-21.693,41.807) P1.12@-22.518,40.982 ; P1.12@-22.393,40.173 cw(c-21.264,39.044) -21.264,40.64 cw(c-21.264,42.236) P1.12@-22.393,41.107 ; v1@-12.588,48.816 cw(c-13.048,48.816) -12.723,48.491 cw(c-12.398,48.166) v1@-12.398,48.626 ; v1@-12.398,49.007 ccw(c-12.398,49.467) -12.072,49.142 ccw(c-11.747,48.816) v1@-12.207,48.816 ; P1_1.12@28.14,40.64 30.426,40.64 v1(38.602,48.816) 43.151,53.365 45.465,53.365 U2_1.30@47.924,55.825 ; P1_1.12@28.482,40.298 cw(c29.307,39.473) 29.307,40.64 cw(c29.307,41.807) P1_1.12@28.482,40.982 ; P1_1.12@28.607,40.173 cw(c29.736,39.044) 29.736,40.64 cw(c29.736,42.236) P1_1.12@28.607,41.107 ; v1@38.412,48.816 cw(c37.952,48.816) 38.277,48.491 cw(c38.602,48.166) v1@38.602,48.626 ; v1@38.602,49.007 ccw(c38.602,49.467) 38.928,49.142 ccw(c39.253,48.816) v1@38.793,48.816
  Bottom Layer w0.178: v1@-12.532,48.951 ccw(c-12.697,49.116) -12.464,49.116 ; -12.464,49.437 ccw(c-11.777,49.437) v1@-12.263,48.951 ; v1(-12.398,48.816) -12.464,48.883 -12.464,61.859 -1.27,73.053 ; P5.3@-1.522,73.43 cw(c-1.678,73.053) -1.27,73.053 ; P5.3@-1.27,74.041 -1.27,73.053 ; P5.3@-1.27,74.422 P5.3@-1.079,74.612 ; P5.3@-1.018,73.43 ccw(c-0.862,73.053) -1.27,73.053 ; v1@38.468,48.951 ccw(c38.303,49.116) 38.536,49.116 ; 38.536,49.437 ccw(c39.223,49.437) v1@38.737,48.951 ; v1(38.602,48.816) 38.536,48.883 38.536,61.859 49.73,73.053 ; P5_1.3@49.478,73.43 cw(c49.322,73.053) 49.73,73.053 ; P5_1.3@49.73,74.041 49.73,73.053 ; P5_1.3@49.73,74.422 P5_1.3@49.92,74.612 ; P5_1.3@49.982,73.43 ccw(c50.138,73.053) 49.73,73.053
PA10: P1.13 P1_1.13 P5.2 P5_1.2 U2.31 U2_1.31 | length 131.6
  Top Layer w0.178: P1.13@-22.86,38.1 -21.844,38.1 ; P1.13@-22.256,37.832 cw(c-21.844,37.65) -21.844,38.1 ; P1.13@-22.256,38.368 ccw(c-21.844,38.55) -21.844,38.1 ; v1@-13.201,46.934 cw(c-13.66,46.934) -13.335,46.609 cw(c-13.01,46.284) v1@-13.01,46.743 ; v1@-13.01,47.124 ccw(c-13.01,47.584) -12.685,47.259 ccw(c-12.36,46.934) v1@-12.82,46.934 ; U2.31@-2.722,55.471 -5.184,53.01 -6.934,53.01 v1(-13.01,46.934) -21.844,38.1 ; P1_1.13@28.14,38.1 29.156,38.1 v1(37.99,46.934) 44.066,53.01 45.816,53.01 U2_1.31@48.278,55.471 ; P1_1.13@28.744,37.832 cw(c29.156,37.65) 29.156,38.1 cw(c29.156,38.55) P1_1.13@28.744,38.368 ; v1@37.799,46.934 cw(c37.34,46.934) 37.665,46.609 cw(c37.99,46.284) v1@37.99,46.743 ; v1@37.99,47.124 ccw(c37.99,47.584) 38.315,47.259 ccw(c38.64,46.934) v1@38.18,46.934
  Bottom Layer w0.178: v1@-13.145,47.069 ccw(c-13.47,47.394) -13.01,47.394 ccw(c-12.55,47.394) v1@-12.875,47.069 ; v1(-13.01,46.934) -13.01,61.92 -3.81,71.12 P5.2@-3.81,74.041 ; P5.2@-4.277,73.574 cw(c-5.406,72.445) -3.81,72.445 cw(c-2.214,72.445) P5.2@-3.343,73.574 ; P5.2@-4.152,73.699 cw(c-4.977,72.874) -3.81,72.874 cw(c-2.643,72.874) P5.2@-3.468,73.699 ; v1@37.855,47.069 ccw(c37.53,47.394) 37.99,47.394 ccw(c38.45,47.394) v1@38.125,47.069 ; v1(37.99,46.934) 37.99,61.92 47.19,71.12 P5_1.2@47.19,74.041 ; P5_1.2@46.723,73.574 cw(c45.594,72.445) 47.19,72.445 cw(c48.786,72.445) P5_1.2@47.657,73.574 ; P5_1.2@46.848,73.699 cw(c46.023,72.874) 47.19,72.874 cw(c48.357,72.874) P5_1.2@47.532,73.699
PA11: P1.14 P1_1.14 R6.1 R6_1.1 U2.32 U2_1.32 | length 128.9
  Top Layer w0.178: P1.14@-22.86,35.56 -22.86,35.814 -6.02,52.654 -4.832,52.654 U2.32@-2.369,55.118 ; P1.14@-22.86,36.043 ccw(c-22.86,36.597) -22.469,36.205 ; P1.14@-22.86,36.221 ccw(c-22.86,37.204) -22.165,36.509 ; P1.14@-22.732,35.56 cw(c-21.811,35.56) -22.462,36.212 ; P1.14@-22.555,35.56 cw(c-21.204,35.56) -22.159,36.515 ; P1.14@-22.377,35.56 cw(c-20.597,35.56) -21.855,36.819 ; P1.14@-22.199,35.56 cw(c-19.99,35.56) -21.552,37.122 ; v1@-15.071,43.793 cw(c-15.531,43.793) -15.206,43.468 cw(c-14.881,43.143) v1@-14.881,43.603 ; v1@-14.994,65.159 ccw(c-15.319,65.484) -14.859,65.484 ccw(c-14.399,65.484) v1@-14.724,65.159 ; v1@-14.881,43.984 ccw(c-14.881,44.444) -14.555,44.119 ccw(c-14.23,43.793) v1@-14.69,43.793 ; v1@-14.859,64.983 cw(c-13.361,64.983) R6.1@-14.385,66.076 ; v1(-14.859,65.024) -14.859,65.862 R6.1@-14.478,66.243 ; -14.859,65.394 cw(c-13.746,65.394) R6.1@-14.507,66.206 ; -14.859,65.804 cw(c-14.13,65.804) R6.1@-14.628,66.336 ; -14.827,65.894 ccw(c-15.023,66.09) R6.1@-14.759,66.174 ; -14.823,65.898 cw(c-14.542,65.616) R6.1@-14.542,66.015 ; P1_1.14@28.14,35.56 28.14,35.814 44.98,52.654 46.168,52.654 U2_1.32@48.631,55.118 ; P1_1.14@28.14,36.043 ccw(c28.14,36.597) 28.531,36.205 ; P1_1.14@28.14,36.221 ccw(c28.14,37.204) 28.835,36.509 ; P1_1.14@28.268,35.56 cw(c29.189,35.56) 28.538,36.212 ; P1_1.14@28.445,35.56 cw(c29.796,35.56) 28.841,36.515 ; P1_1.14@28.623,35.56 cw(c30.403,35.56) 29.145,36.819 ; P1_1.14@28.801,35.56 cw(c31.01,35.56) 29.448,37.122 ; v1@35.929,43.793 cw(c35.469,43.793) 35.794,43.468 cw(c36.119,43.143) v1@36.119,43.603 ; v1@36.006,65.159 ccw(c35.681,65.484) 36.141,65.484 ccw(c36.601,65.484) v1@36.276,65.159 ; v1@36.119,43.984 ccw(c36.119,44.444) 36.445,44.119 ccw(c36.77,43.793) v1@36.31,43.793 ; v1@36.141,64.983 cw(c37.639,64.983) R6_1.1@36.615,66.076 ; v1(36.141,65.024) 36.141,65.862 R6_1.1@36.522,66.243 ; 36.141,65.394 cw(c37.254,65.394) R6_1.1@36.493,66.206 ; 36.141,65.804 cw(c36.87,65.804) R6_1.1@36.372,66.336 ; 36.173,65.894 ccw(c35.977,66.09) R6_1.1@36.241,66.174 ; 36.177,65.898 cw(c36.458,65.616) R6_1.1@36.458,66.015
  Bottom Layer w0.178: v1@-15.015,43.928 ccw(c-15.331,44.244) -14.884,44.244 ; v1@-14.994,64.889 cw(c-15.258,64.625) -14.884,64.625 ; -14.884,44.263 ccw(c-14.411,44.263) v1@-14.746,43.928 ; -14.884,64.503 cw(c-14.338,64.503) v1@-14.724,64.889 ; v1(-14.881,43.793) -14.884,43.797 -14.884,64.999 v1(-14.859,65.024) ; v1@35.985,43.928 ccw(c35.669,44.244) 36.116,44.244 ; v1@36.006,64.889 cw(c35.742,64.625) 36.116,64.625 ; 36.116,44.263 ccw(c36.589,44.263) v1@36.254,43.928 ; 36.116,64.503 cw(c36.662,64.503) v1@36.276,64.889 ; v1(36.119,43.793) 36.116,43.797 36.116,64.999 v1(36.141,65.024)
PA12: P1.15 P1_1.15 R7.1 R7_1.1 R8.1 R8_1.1 U2.33 U2_1.33 | length 134.9
  Top Layer w0.178: P1.15@-22.86,33.02 -20.244,35.636 -20.244,37.414 -5.359,52.299 -4.481,52.299 U2.33@-2.015,54.764 ; P1.15@-22.86,33.503 ccw(c-22.86,34.67) -22.035,33.845 ccw(c-21.21,33.02) P1.15@-22.377,33.02 ; P1.15@-22.86,33.681 ccw(c-22.86,35.277) -21.731,34.149 ccw(c-20.603,33.02) P1.15@-22.199,33.02 ; R8.1@-17.272,66.243 R7.1@-15.875,66.243 -15.875,65.151 v1(-15.748,65.024) ; R8.1@-17.047,66.082 cw(c-16.657,65.691) -16.657,66.243 cw(c-16.657,66.795) R8.1@-17.047,66.405 ; R7.1@-16.1,66.082 ccw(c-16.49,65.691) -16.49,66.243 ccw(c-16.49,66.795) R7.1@-16.1,66.405 ; -16.036,41.622 ccw(c-16.578,42.164) v1@-15.811,42.164 ; R7.1@-16.037,66.082 cw(c-16.427,65.691) -15.875,65.691 cw(c-15.323,65.691) R7.1@-15.713,66.082 ; -15.875,65.361 ccw(c-15.411,65.361) v1@-15.739,65.033 ; -15.875,65.791 ccw(c-14.981,65.791) v1@-15.613,65.159 ; v1@-15.621,42.355 ccw(c-15.621,43.121) -15.079,42.579 ; P1_1.15@28.14,33.02 30.756,35.636 30.756,37.414 45.641,52.299 46.519,52.299 U2_1.33@48.985,54.764 ; P1_1.15@28.14,33.503 ccw(c28.14,34.67) 28.965,33.845 ccw(c29.79,33.02) P1_1.15@28.623,33.02 ; P1_1.15@28.14,33.681 ccw(c28.14,35.277) 29.269,34.149 ccw(c30.397,33.02) P1_1.15@28.801,33.02 ; R8_1.1@33.728,66.243 R7_1.1@35.125,66.243 35.125,65.151 v1(35.252,65.024) ; R8_1.1@33.953,66.082 cw(c34.343,65.691) 34.343,66.243 cw(c34.343,66.795) R8_1.1@33.953,66.405 ; R7_1.1@34.9,66.082 ccw(c34.51,65.691) 34.51,66.243 ccw(c34.51,66.795) R7_1.1@34.9,66.405 ; R7_1.1@34.963,66.082 cw(c34.573,65.691) 35.125,65.691 cw(c35.677,65.691) R7_1.1@35.287,66.082 ; 34.964,41.622 ccw(c34.422,42.164) v1@35.188,42.164 ; 35.125,65.361 ccw(c35.589,65.361) v1@35.261,65.033 ; 35.125,65.791 ccw(c36.019,65.791) v1@35.387,65.159 ; v1@35.379,42.355 ccw(c35.379,43.121) 35.921,42.579
  Bottom Layer w0.178: v1@-15.883,64.889 cw(c-16.515,64.257) -15.621,64.257 ; v1@-15.757,65.015 cw(c-16.085,64.687) -15.621,64.687 ; v1@-15.756,42.299 ccw(c-16.081,42.624) -15.621,42.624 ccw(c-15.161,42.624) v1@-15.486,42.299 ; v1(-15.748,65.024) -15.621,64.897 v1(-15.621,42.164) ; v1@35.117,64.889 cw(c34.485,64.257) 35.379,64.257 ; v1@35.243,65.015 cw(c34.915,64.687) 35.379,64.687 ; v1@35.244,42.299 ccw(c34.919,42.624) 35.379,42.624 ccw(c35.839,42.624) v1@35.514,42.299 ; v1(35.252,65.024) 35.379,64.897 v1(35.379,42.164)
PA13: P1.16 P1_1.16 P5.4 P5_1.4 U2.34 U2_1.34 | length 156.6
  Top Layer w0.178: P1.16@-22.86,30.48 -19.888,33.452 -19.888,36.627 -4.572,51.943 -4.129,51.943 U2.34@-1.662,54.41 ; P1.16@-22.86,30.963 ccw(c-22.86,32.13) -22.035,31.305 ccw(c-21.21,30.48) P1.16@-22.377,30.48 ; P1.16@-22.86,31.141 ccw(c-22.86,32.737) -21.731,31.609 ccw(c-20.603,30.48) P1.16@-22.199,30.48 ; -11.845,44.67 ccw(c-12.387,45.212) v1@-11.62,45.212 ; v1@-11.43,45.402 ccw(c-11.43,46.169) -10.888,45.627 ; P1_1.16@28.14,30.48 31.112,33.452 31.112,36.627 46.428,51.943 46.871,51.943 U2_1.34@49.338,54.41 ; P1_1.16@28.14,30.963 ccw(c28.14,32.13) 28.965,31.305 ccw(c29.79,30.48) P1_1.16@28.623,30.48 ; P1_1.16@28.14,31.141 ccw(c28.14,32.737) 29.269,31.609 ccw(c30.397,30.48) P1_1.16@28.801,30.48 ; 39.155,44.67 ccw(c38.613,45.212) v1@39.379,45.212 ; v1@39.57,45.402 ccw(c39.57,46.169) 40.112,45.627
  Bottom Layer w0.178: v1@-11.565,45.347 ccw(c-11.89,45.672) -11.43,45.672 ccw(c-10.97,45.672) v1@-11.295,45.347 ; v1(-11.43,45.212) -11.43,62.39 -1.836,71.984 -0.787,71.984 P5.4@1.27,74.041 ; P5.4@0.609,74.041 cw(c-0.987,74.041) 0.141,72.912 cw(c1.27,71.784) P5.4@1.27,73.38 ; P5.4@0.787,74.041 cw(c-0.38,74.041) 0.445,73.216 cw(c1.27,72.391) P5.4@1.27,73.558 ; v1@39.435,45.347 ccw(c39.11,45.672) 39.57,45.672 ccw(c40.03,45.672) v1@39.705,45.347 ; v1(39.57,45.212) 39.57,62.39 49.164,71.984 50.213,71.984 P5_1.4@52.27,74.041 ; P5_1.4@51.609,74.041 cw(c50.013,74.041) 51.141,72.912 cw(c52.27,71.784) P5_1.4@52.27,73.38 ; P5_1.4@51.787,74.041 cw(c50.62,74.041) 51.445,73.216 cw(c52.27,72.391) P5_1.4@52.27,73.558
PA14: P1.17 P1_1.17 P5.5 P5_1.5 U2.37 U2_1.37 | length 169.9
  Top Layer w0.178: P1.17@-22.86,27.94 -19.533,31.267 -19.533,35.839 -5.512,49.86 -2.337,49.86 0.955,53.152 U2.37@0.955,53.703 ; P1.17@-22.86,28.423 ccw(c-22.86,29.59) -22.035,28.765 ccw(c-21.21,27.94) P1.17@-22.377,27.94 ; P1.17@-22.86,28.601 ccw(c-22.86,30.197) -21.731,29.069 ccw(c-20.603,27.94) P1.17@-22.199,27.94 ; -10.956,44.416 ccw(c-11.498,44.958) v1@-10.731,44.958 ; v1@-10.541,45.148 ccw(c-10.541,45.915) -9.999,45.373 ; P1_1.17@28.14,27.94 31.467,31.267 31.467,35.839 45.488,49.86 48.663,49.86 51.955,53.152 U2_1.37@51.955,53.703 ; P1_1.17@28.14,28.423 ccw(c28.14,29.59) 28.965,28.765 ccw(c29.79,27.94) P1_1.17@28.623,27.94 ; P1_1.17@28.14,28.601 ccw(c28.14,30.197) 29.269,29.069 ccw(c30.397,27.94) P1_1.17@28.801,27.94 ; 40.044,44.416 ccw(c39.502,44.958) v1@40.268,44.958 ; v1@40.459,45.148 ccw(c40.459,45.915) 41.001,45.373
  Bottom Layer w0.178: v1@-10.676,45.093 ccw(c-11.001,45.418) -10.541,45.418 ccw(c-10.081,45.418) v1@-10.406,45.093 ; v1(-10.541,44.958) -10.541,62.776 -1.689,71.628 1.397,71.628 P5.5@3.81,74.041 ; P5.5@3.149,74.041 cw(c1.553,74.041) 2.681,72.912 cw(c3.81,71.784) P5.5@3.81,73.38 ; P5.5@3.327,74.041 cw(c2.16,74.041) 2.985,73.216 cw(c3.81,72.391) P5.5@3.81,73.558 ; v1@40.324,45.093 ccw(c39.999,45.418) 40.459,45.418 ccw(c40.919,45.418) v1@40.594,45.093 ; v1(40.459,44.958) 40.459,62.776 49.311,71.628 52.397,71.628 P5_1.5@54.81,74.041 ; P5_1.5@54.149,74.041 cw(c52.553,74.041) 53.681,72.912 cw(c54.81,71.784) P5_1.5@54.81,73.38 ; P5_1.5@54.327,74.041 cw(c53.16,74.041) 53.985,73.216 cw(c54.81,72.391) P5_1.5@54.81,73.558
PA15: P1.18 P1_1.18 U2.38 U2_1.38 | length 92.2
  Top Layer w0.178: P1.18@-22.86,25.4 -19.177,29.083 -19.177,34.808 -4.481,49.505 -2.184,49.505 -0.254,51.435 1.143,51.435 2.413,52.705 2.413,52.952 U2.38@1.308,54.057 ; P1.18@-22.86,25.883 ccw(c-22.86,27.05) -22.035,26.225 ccw(c-21.21,25.4) P1.18@-22.377,25.4 ; P1.18@-22.86,26.061 ccw(c-22.86,27.657) -21.731,26.529 ccw(c-20.603,25.4) P1.18@-22.199,25.4 ; P1_1.18@28.14,25.4 31.823,29.083 31.823,34.808 46.519,49.505 48.816,49.505 50.746,51.435 52.143,51.435 53.413,52.705 53.413,52.952 U2_1.38@52.308,54.057 ; P1_1.18@28.14,25.883 ccw(c28.14,27.05) 28.965,26.225 ccw(c29.79,25.4) P1_1.18@28.623,25.4 ; P1_1.18@28.14,26.061 ccw(c28.14,27.657) 29.269,26.529 ccw(c30.397,25.4) P1_1.18@28.801,25.4
PB0: P2.3 P2_1.3 U2.18 U2_1.18 | length 85.1
  Top Layer w0.178: v1@-6.604,64.96 cw(c-6.604,63.647) -5.675,64.576 ; v1@-6.604,65.138 cw(c-6.604,64.254) -5.979,64.879 ; v1(-6.604,65.151) -6.25,65.151 U2.18@-2.722,61.623 ; v1@-6.604,65.316 cw(c-6.604,64.861) -6.282,65.183 ; v1@44.396,64.96 cw(c44.396,63.647) 45.325,64.576 ; v1@44.396,65.138 cw(c44.396,64.254) 45.021,64.879 ; v1(44.396,65.151) 44.75,65.151 U2_1.18@48.278,61.623 ; v1@44.396,65.316 cw(c44.396,64.861) 44.718,65.183
  Bottom Layer w0.178: v1(-6.604,65.151) 18.034,65.151 21.463,68.58 ; v1@-6.469,65.016 cw(c-6.144,64.691) -6.144,65.151 cw(c-6.144,65.611) v1@-6.469,65.286 ; P2.3@22.349,68.161 ccw(c21.463,67.435) 21.463,68.58 ; P2.3@22.349,68.999 cw(c21.463,69.725) 21.463,68.58 ; P2.3@22.486,68.274 ccw(c21.839,67.743) 21.839,68.58 ccw(c21.839,69.417) P2.3@22.486,68.886 ; P2.3@22.86,68.58 21.463,68.58 ; v1(44.396,65.151) 69.034,65.151 72.463,68.58 ; v1@44.531,65.016 cw(c44.856,64.691) 44.856,65.151 cw(c44.856,65.611) v1@44.531,65.286 ; P2_1.3@73.349,68.161 ccw(c72.463,67.435) 72.463,68.58 ; P2_1.3@73.349,68.999 cw(c72.463,69.725) 72.463,68.58 ; P2_1.3@73.486,68.274 ccw(c72.839,67.743) 72.839,68.58 ccw(c72.839,69.417) P2_1.3@73.486,68.886 ; P2_1.3@73.86,68.58 72.463,68.58
PB1: P2.4 P2_1.4 U2.19 U2_1.19 | length 82.5
  Top Layer w0.178: v1(-6.858,64.262) -6.069,64.262 U2.19@-3.076,61.269 ; v1@-6.723,64.127 cw(c-6.398,63.802) -6.398,64.262 cw(c-6.398,64.722) v1@-6.723,64.397 ; v1(44.142,64.262) 44.931,64.262 U2_1.19@47.924,61.269 ; v1@44.277,64.127 cw(c44.602,63.802) 44.602,64.262 cw(c44.602,64.722) v1@44.277,64.397
  Bottom Layer w0.178: v1(-6.858,64.262) 18.542,64.262 20.32,66.04 P2.4@22.86,66.04 ; v1@-6.723,64.127 cw(c-6.398,63.802) -6.398,64.262 cw(c-6.398,64.722) v1@-6.723,64.397 ; P2.4@22.393,65.573 ccw(c21.264,64.444) 21.264,66.04 ccw(c21.264,67.636) P2.4@22.393,66.507 ; P2.4@22.518,65.698 ccw(c21.693,64.873) 21.693,66.04 ccw(c21.693,67.207) P2.4@22.518,66.382 ; v1(44.142,64.262) 69.542,64.262 71.32,66.04 P2_1.4@73.86,66.04 ; v1@44.277,64.127 cw(c44.602,63.802) 44.602,64.262 cw(c44.602,64.722) v1@44.277,64.397 ; P2_1.4@73.393,65.573 ccw(c72.264,64.444) 72.264,66.04 ccw(c72.264,67.636) P2_1.4@73.393,66.507 ; P2_1.4@73.518,65.698 ccw(c72.693,64.873) 72.693,66.04 ccw(c72.693,67.207) P2_1.4@73.518,66.382
PB2: P2.5 P2_1.5 U2.20 U2_1.20 | length 80
  Top Layer w0.178: v1(-6.858,63.246) -5.76,63.246 U2.20@-3.429,60.916 ; v1@-6.723,63.111 cw(c-6.398,62.786) -6.398,63.246 cw(c-6.398,63.706) v1@-6.723,63.381 ; v1(44.142,63.246) 45.24,63.246 U2_1.20@47.571,60.916 ; v1@44.277,63.111 cw(c44.602,62.786) 44.602,63.246 cw(c44.602,63.706) v1@44.277,63.381
  Bottom Layer w0.178: v1(-6.858,63.246) 18.669,63.246 18.923,63.5 P2.5@22.86,63.5 ; v1@-6.723,63.111 cw(c-6.398,62.786) -6.398,63.246 cw(c-6.398,63.706) v1@-6.723,63.381 ; P2.5@22.393,63.033 ccw(c21.264,61.904) 21.264,63.5 ccw(c21.264,65.096) P2.5@22.393,63.967 ; P2.5@22.518,63.158 ccw(c21.693,62.333) 21.693,63.5 ccw(c21.693,64.667) P2.5@22.518,63.842 ; v1(44.142,63.246) 69.669,63.246 69.923,63.5 P2_1.5@73.86,63.5 ; v1@44.277,63.111 cw(c44.602,62.786) 44.602,63.246 cw(c44.602,63.706) v1@44.277,63.381 ; P2_1.5@73.393,63.033 ccw(c72.264,61.904) 72.264,63.5 ccw(c72.264,65.096) P2_1.5@73.393,63.967 ; P2_1.5@73.518,63.158 ccw(c72.693,62.333) 72.693,63.5 ccw(c72.693,64.667) P2_1.5@73.518,63.842
PB3: P2.6 P2_1.6 U2.39 U2_1.39 | length 61.9
  Top Layer w0.178: U2.39@1.662,54.41 4.383,51.689 v1(5.715,51.689) ; v1@5.58,51.554 ccw(c5.255,51.229) 5.255,51.689 ccw(c5.255,52.149) v1@5.58,51.824 ; U2_1.39@52.662,54.41 55.383,51.689 v1(56.715,51.689) ; v1@56.58,51.554 ccw(c56.255,51.229) 56.255,51.689 ccw(c56.255,52.149) v1@56.58,51.824
  Bottom Layer w0.178: v1@5.58,51.824 ccw(c5.255,52.149) 5.715,52.149 ccw(c6.175,52.149) v1@5.85,51.824 ; v1(5.715,51.689) 5.715,53.34 9.652,57.277 18.034,57.277 21.717,60.96 ; P2.6@22.287,60.63 ccw(c21.717,60.303) 21.717,60.96 ; P2.6@22.287,61.29 cw(c21.717,61.617) 21.717,60.96 ; P2.6@22.441,60.719 ccw(c22.024,60.479) 22.024,60.96 ccw(c22.024,61.441) P2.6@22.441,61.201 ; P2.6@22.86,60.96 21.717,60.96 ; v1@56.58,51.824 ccw(c56.255,52.149) 56.715,52.149 ccw(c57.175,52.149) v1@56.85,51.824 ; v1(56.715,51.689) 56.715,53.34 60.652,57.277 69.034,57.277 72.717,60.96 ; P2_1.6@73.287,60.63 ccw(c72.717,60.303) 72.717,60.96 ; P2_1.6@73.287,61.29 cw(c72.717,61.617) 72.717,60.96 ; P2_1.6@73.441,60.719 ccw(c73.024,60.479) 73.024,60.96 ccw(c73.024,61.441) P2_1.6@73.441,61.201 ; P2_1.6@73.86,60.96 72.717,60.96
PB4: P2.7 P2_1.7 U2.40 U2_1.40 | length 59.3
  Top Layer w0.178: U2.40@2.015,54.764 4.455,52.324 6.604,52.324 v1(6.731,52.197) ; 5.964,52.324 cw(c5.964,51.43) v1@6.596,52.062 ; 6.394,52.324 cw(c6.394,51.86) v1@6.722,52.188 ; U2_1.40@53.015,54.764 55.455,52.324 57.604,52.324 v1(57.731,52.197) ; 56.964,52.324 cw(c56.964,51.43) v1@57.596,52.062 ; 57.394,52.324 cw(c57.394,51.86) v1@57.722,52.188
  Bottom Layer w0.178: v1@6.596,52.332 ccw(c6.271,52.657) 6.731,52.657 ccw(c7.191,52.657) v1@6.866,52.332 ; v1(6.731,52.197) 6.731,53.848 9.6,56.717 20.014,56.717 21.717,58.42 ; P2.7@22.287,58.09 ccw(c21.717,57.763) 21.717,58.42 ; P2.7@22.287,58.75 cw(c21.717,59.077) 21.717,58.42 ; P2.7@22.441,58.179 ccw(c22.024,57.939) 22.024,58.42 ccw(c22.024,58.901) P2.7@22.441,58.661 ; P2.7@22.86,58.42 21.717,58.42 ; v1@57.596,52.332 ccw(c57.271,52.657) 57.731,52.657 ccw(c58.191,52.657) v1@57.866,52.332 ; v1(57.731,52.197) 57.731,53.848 60.6,56.717 71.014,56.717 72.717,58.42 ; P2_1.7@73.287,58.09 ccw(c72.717,57.763) 72.717,58.42 ; P2_1.7@73.287,58.75 cw(c72.717,59.077) 72.717,58.42 ; P2_1.7@73.441,58.179 ccw(c73.024,57.939) 73.024,58.42 ccw(c73.024,58.901) P2_1.7@73.441,58.661 ; P2_1.7@73.86,58.42 72.717,58.42
PB5: P2.8 P2_1.8 U2.41 U2_1.41 | length 57.9
  Top Layer w0.178: U2.41@2.369,55.118 4.654,52.832 v1(7.62,52.832) ; v1@7.485,52.697 ccw(c7.16,52.372) 7.16,52.832 ccw(c7.16,53.292) v1@7.485,52.967 ; U2_1.41@53.369,55.118 55.654,52.832 v1(58.62,52.832) ; v1@58.485,52.697 ccw(c58.16,52.372) 58.16,52.832 ccw(c58.16,53.292) v1@58.485,52.967
  Bottom Layer w0.178: v1@7.485,52.967 ccw(c7.16,53.292) 7.62,53.292 ccw(c8.08,53.292) v1@7.755,52.967 ; v1(7.62,52.832) 7.62,53.594 9.906,55.88 P2.8@22.86,55.88 ; P2.8@22.393,55.413 ccw(c21.264,54.284) 21.264,55.88 ccw(c21.264,57.476) P2.8@22.393,56.347 ; P2.8@22.518,55.538 ccw(c21.693,54.713) 21.693,55.88 ccw(c21.693,57.047) P2.8@22.518,56.222 ; v1@58.485,52.967 ccw(c58.16,53.292) 58.62,53.292 ccw(c59.08,53.292) v1@58.755,52.967 ; v1(58.62,52.832) 58.62,53.594 60.906,55.88 P2_1.8@73.86,55.88 ; P2_1.8@73.393,55.413 ccw(c72.264,54.284) 72.264,55.88 ccw(c72.264,57.476) P2_1.8@73.393,56.347 ; P2_1.8@73.518,55.538 ccw(c72.693,54.713) 72.693,55.88 ccw(c72.693,57.047) P2_1.8@73.518,56.222
PB6: P2.9 P2_1.9 U2.42 U2_1.42 | length 56.9
  Top Layer w0.178: U2.42@2.722,55.471 4.726,53.467 v1(8.763,53.467) ; v1@8.628,53.332 ccw(c8.303,53.007) 8.303,53.467 ccw(c8.303,53.927) v1@8.628,53.602 ; U2_1.42@53.722,55.471 55.726,53.467 v1(59.763,53.467) ; v1@59.628,53.332 ccw(c59.303,53.007) 59.303,53.467 ccw(c59.303,53.927) v1@59.628,53.602
  Bottom Layer w0.178: v1@8.628,53.602 ccw(c8.303,53.927) 8.763,53.927 ccw(c9.223,53.927) v1@8.898,53.602 ; v1(8.763,53.467) 8.763,54.112 9.642,54.991 21.209,54.991 P2.9@22.86,53.34 ; P2.9@22.199,53.34 ccw(c20.603,53.34) 21.731,54.469 ccw(c22.86,55.597) P2.9@22.86,54.001 ; P2.9@22.377,53.34 ccw(c21.21,53.34) 22.035,54.165 ccw(c22.86,54.99) P2.9@22.86,53.823 ; v1@59.628,53.602 ccw(c59.303,53.927) 59.763,53.927 ccw(c60.223,53.927) v1@59.898,53.602 ; v1(59.763,53.467) 59.763,54.112 60.642,54.991 72.209,54.991 P2_1.9@73.86,53.34 ; P2_1.9@73.199,53.34 ccw(c71.603,53.34) 72.731,54.469 ccw(c73.86,55.597) P2_1.9@73.86,54.001 ; P2_1.9@73.377,53.34 ccw(c72.21,53.34) 73.035,54.165 ccw(c73.86,54.99) P2_1.9@73.86,53.823
PB7: P2.10 P2_1.10 U2.43 U2_1.43 | length 55.3
  Top Layer w0.178: U2.43@3.076,55.825 4.672,54.229 v1(9.652,54.229) ; v1@9.517,54.094 ccw(c9.192,53.769) 9.192,54.229 ccw(c9.192,54.689) v1@9.517,54.364 ; U2_1.43@54.076,55.825 55.672,54.229 v1(60.652,54.229) ; v1@60.517,54.094 ccw(c60.192,53.769) 60.192,54.229 ccw(c60.192,54.689) v1@60.517,54.364
  Bottom Layer w0.178: v1(9.652,54.229) 19.431,54.229 P2.10@22.86,50.8 ; v1@9.787,54.094 cw(c10.112,53.769) 10.112,54.229 cw(c10.112,54.689) v1@9.787,54.364 ; P2.10@22.199,50.8 ccw(c20.603,50.8) 21.731,51.929 ccw(c22.86,53.057) P2.10@22.86,51.461 ; P2.10@22.377,50.8 ccw(c21.21,50.8) 22.035,51.625 ccw(c22.86,52.45) P2.10@22.86,51.283 ; v1(60.652,54.229) 70.431,54.229 P2_1.10@73.86,50.8 ; v1@60.787,54.094 cw(c61.112,53.769) 61.112,54.229 cw(c61.112,54.689) v1@60.787,54.364 ; P2_1.10@73.199,50.8 ccw(c71.603,50.8) 72.731,51.929 ccw(c73.86,53.057) P2_1.10@73.86,51.461 ; P2_1.10@73.377,50.8 ccw(c72.21,50.8) 73.035,51.625 ccw(c73.86,52.45) P2_1.10@73.86,51.283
